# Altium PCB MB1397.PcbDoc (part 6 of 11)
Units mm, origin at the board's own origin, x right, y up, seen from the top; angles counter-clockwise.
Board outline 118.24 x 172.86 mm, 6 copper layers (Top Layer, L2_GND, L3_VCC, L4_SIG, L5_GND, Bottom Layer), stack 1.631 mm thick; 819 components, 632 nets, 2875 pads, 1523 vias.
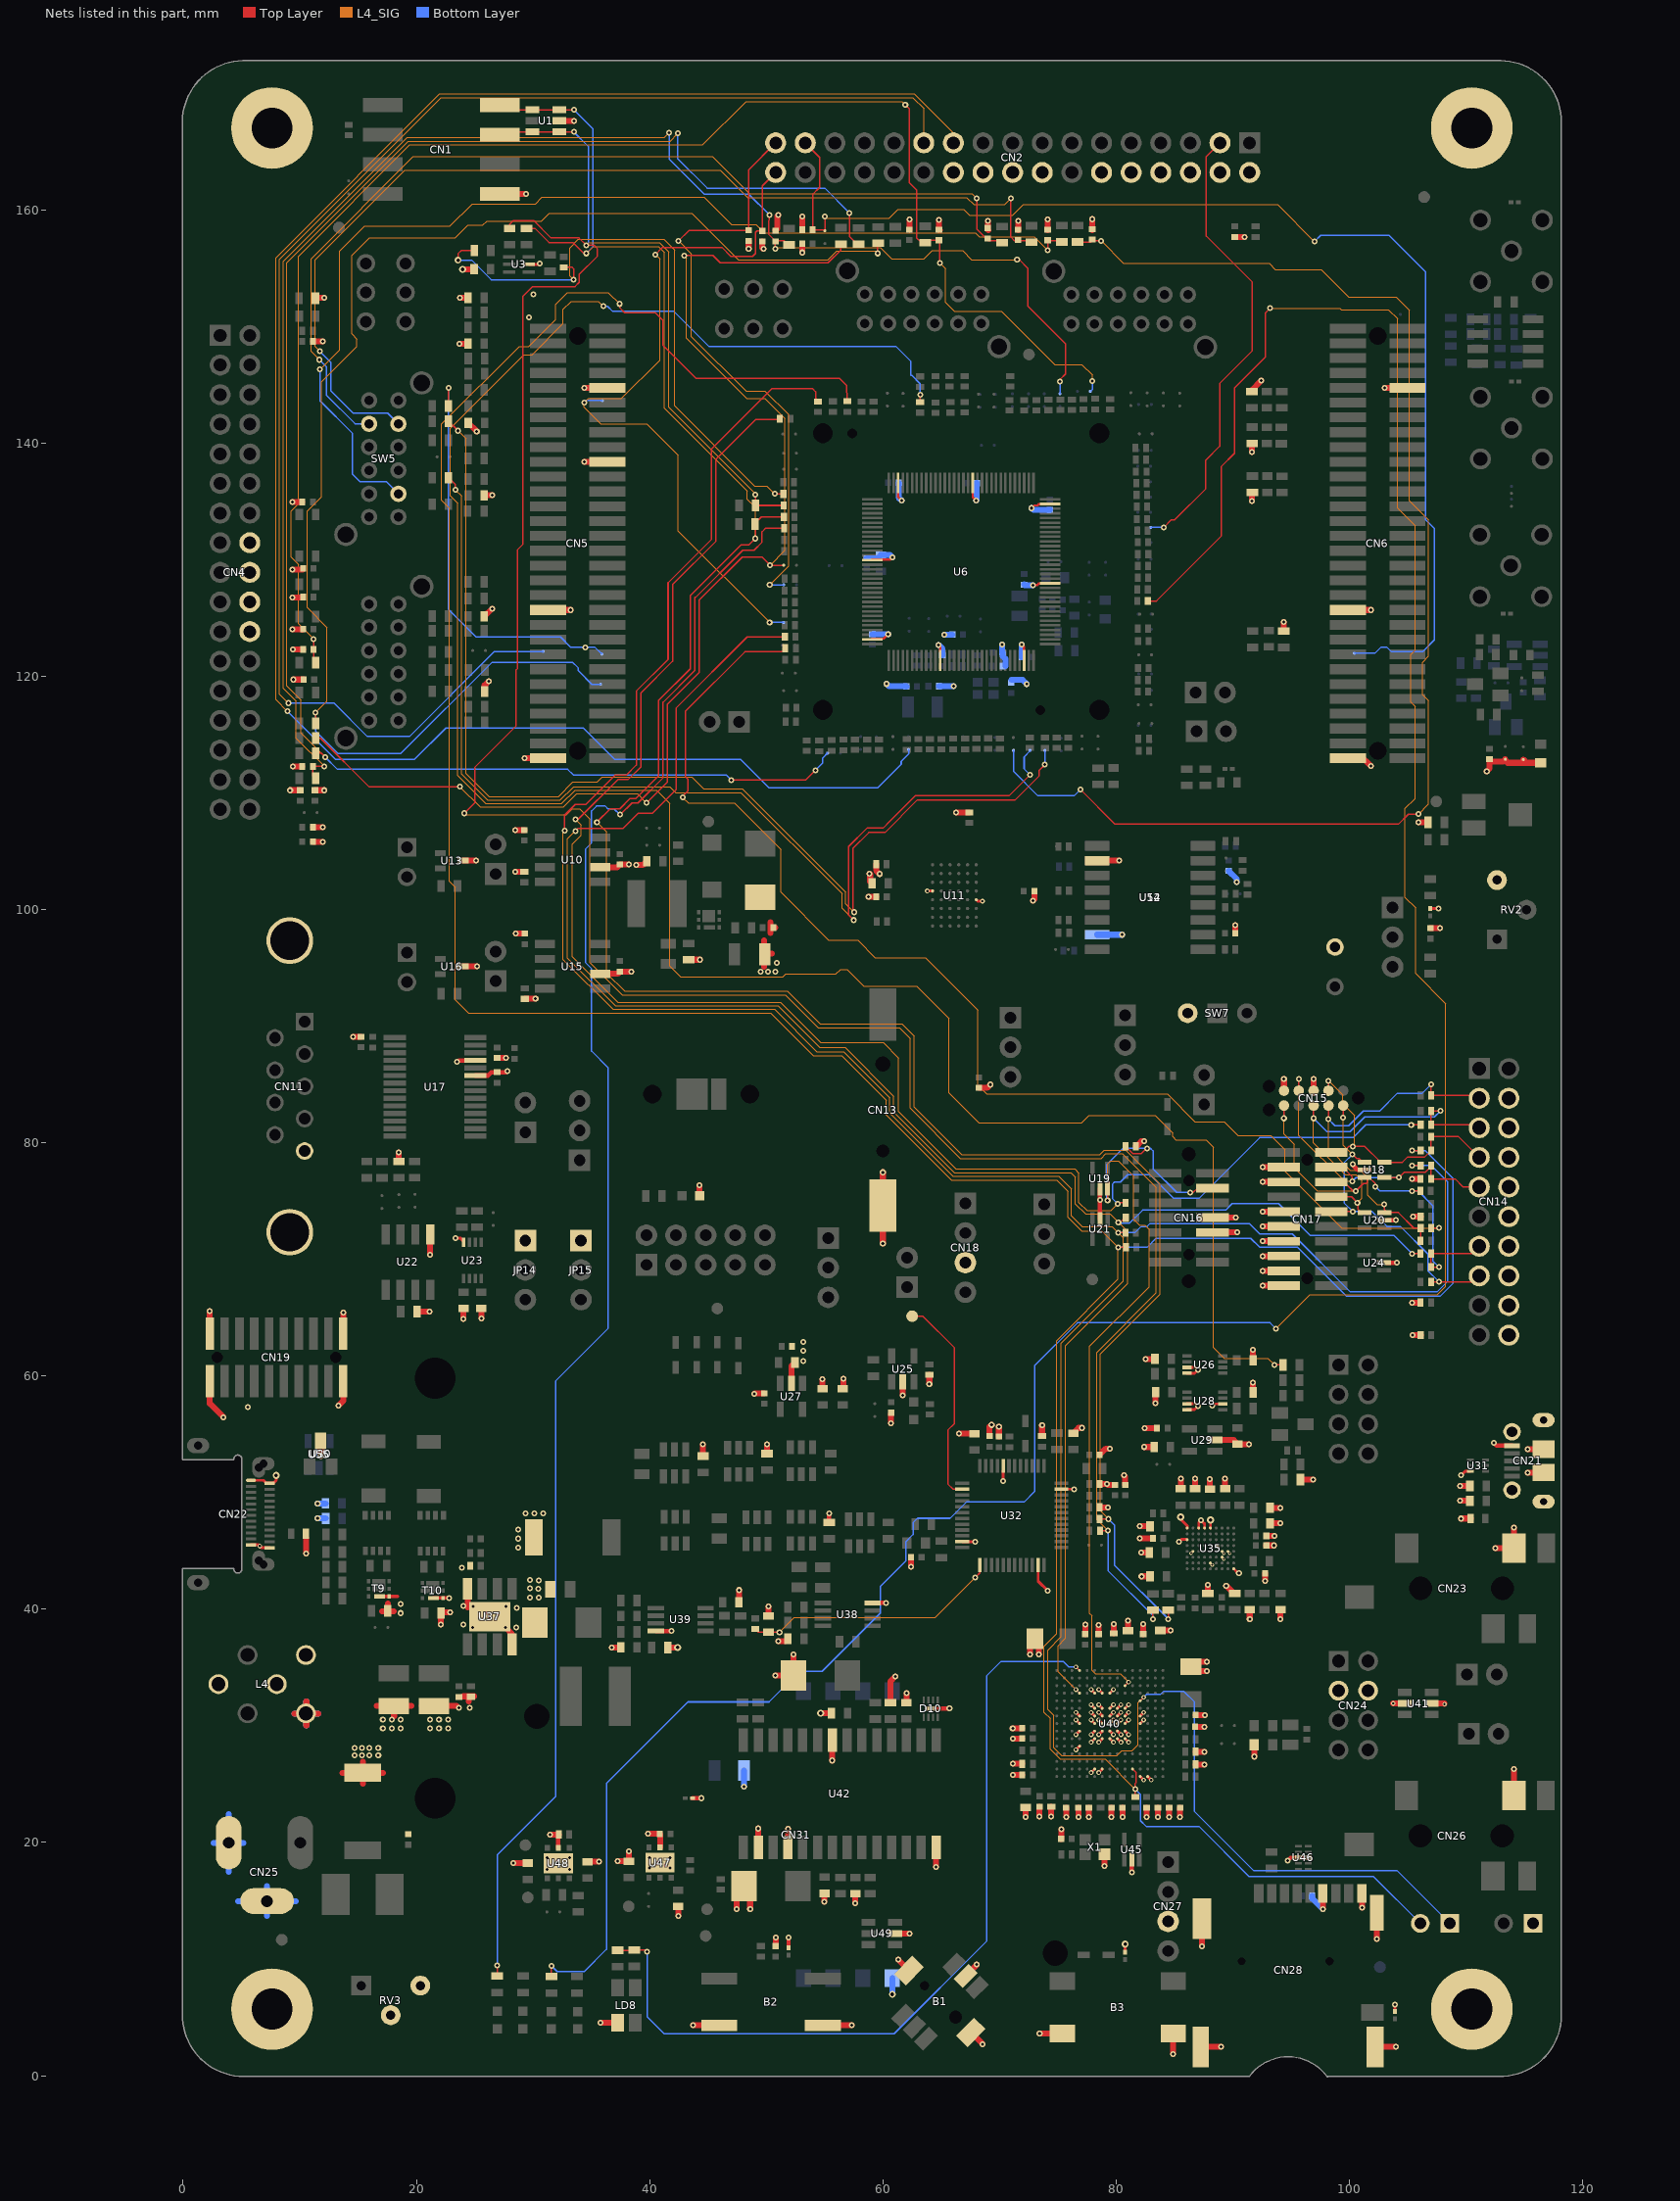
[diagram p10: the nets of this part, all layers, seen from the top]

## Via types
v1: diameter 0.508, hole 0.254, Top Layer to Bottom Layer, tented both sides, 1330 vias
v2: diameter 0.406, hole 0.203, Top Layer to Bottom Layer, tented both sides, 115 vias
v3: diameter 0.508, hole 0.254, Top Layer to Bottom Layer, 33 vias
v4: diameter 0.305, hole 0.152, Top Layer to Bottom Layer, tented both sides, 26 vias
v5: diameter 0.61, hole 0.305, Top Layer to Bottom Layer, tented both sides, 14 vias
v6: diameter 0.61, hole 0.33, Top Layer to Bottom Layer, tented both sides, 2 vias
v7: diameter 0.381, hole 0.203, Top Layer to Bottom Layer, tented both sides, 2 vias
v8: diameter 0.508, hole 0.203, Top Layer to Bottom Layer, tented both sides, 1 vias

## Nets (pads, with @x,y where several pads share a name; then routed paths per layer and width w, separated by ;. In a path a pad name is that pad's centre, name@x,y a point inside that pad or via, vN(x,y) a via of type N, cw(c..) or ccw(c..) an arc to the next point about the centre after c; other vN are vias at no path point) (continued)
GND: B1.5 B1.7 B1.8 B2.3 B2.4 B3.1 B3.2 C1.1 C2.1 C3.1 C4.2 C5.1 C6.1 C7.1 C8.1 C9.1 C10.1 C11.1 C12.1 C13.2 C14.2 C15.2 C16.1 C18.2 C21.2 C22.2 C23.1 C24.1 C25.2 C26.1 C29.1 C31.1 C32.2 C33.2 C34.1 C37.1 C38.1 C39.1 C40.2 C41.2 C42.1 C44.2 C45.1 C46.1 C47.2 C48.2 C49.1 C50.2 C51.1 C52.2 C53.2 C54.1 C56.1 C58.2 C59.1 C61.2 C62.1 C63.1 C64.2 C65.1 C66.2 C67.1 C68.1 C69.2 C70.1 C71.1 C72.1 C73.1 C74.1 C75.1 C76.1 C77.1 C78.1 C79.1 C80.1 C81.2 C82.2 C83.1 C84.1 C85.2 C86.1 C88.1 C89.1 C90.1 C91.1 C92.1 C93.2 C94.2 C96.2 C97.1 C98.1 C100.2 C101.1 C102.1 C104.1 C105.1 C108.1 C109.2 C112.1 C113.1 C114.1 C115.1 C116.1 C117.1 C118.1 C119.1 C120.1 C121.2 C122.1 C123.1 C124.1 C125.1 C126.2 C127.1 C128.1 C130.1 C131.1 C133.1 C134.1 C135.1 C136.1 C137.1 C138.1 C139.1 C140.1 C141.1 C142.1 C143.1 C144.1 C145.1 C146.2 C148.1 C149.1 C150.2 C151.1 C152.2 C153.1 C155.2 C156.1 C157.1 C160.1 C161.1 C162.1 C163.2 C164.1 C165.1 C172.2 C173.1 C174.1 C175.1 C176.1 C177.1 C178.1 C182.1 C183.1 C184.1 C185.1 C186.2 CN1.7 CN2.2 CN2.4 CN2.6 CN2.8 CN2.10 CN2.12 CN2.16 CN2.18 CN2.20 CN2.22 CN4.16 CN4.18 CN4.20 CN4.22 CN5.10 CN5.20 CN5.39 CN5.59 CN6.10 CN6.39 CN6.59 CN11.5 CN11.MT1 CN11.MT2 CN13.2 CN14.4 CN14.6 CN14.8 CN14.10 CN14.12 CN14.14 CN14.16 CN14.18 CN14.20 CN15.3 CN15.5 CN16.5 CN16.7 CN17.3 CN17.5 CN17.9 CN17.11 CN17.13 CN17.15 CN17.17 CN17.19 CN18.3 CN19.1 CN19.2 CN19.19 CN19.20 CN21.5 CN21.6 CN21.7 CN21.8 CN21.9 CN21.10 CN21.11 CN22.A1 CN22.A12 CN22.B1 CN22.B12 CN23.3 CN24.3 CN24.4 CN26.3 CN27.3 CN28.6 CN28.9 CN28.11 CN28.12 CN28.13 CN28.14 CN30.1 CN31.C5 CN31.S1 D10.9 H1.1 H2.1 H5.1 H6.1 JP14.1 JP15.1 L1.1 L4.4 L4.5 L4.6 L7.1 LD6.2 LD8.1 R18.2 R32.1 R56.1 R65.1 R106.1 R156.1 R157.2 R162.1 R163.2 R174.2 R176.1 R177.1 R180.2 R187.1 R190.2 R195.1 R203.1 R212.1 R213.1 R214.1 R217.1 R224.1 R229.1 R230.1 R233.2 R234.2 R236.2 R242.1 R251.1 R255.1 R256.1 R263.1 R264.1 R269.1 R271.1 R272.1 R276.1 R279.1 R280.1 R281.2 R283.1 R286.2 R323.1 RV2.3 RV3.2 RV3.3 SB30.1 SB31.1 SW7.3 T9.4 T9.7 T10.4 T10.7 U1.2 U3.5 U6.12 U6.30 U6.46 U6.63 U6.78 U6.94 U6.110 U6.127 U10.2 U11.D1 U11.E6 U12.10 U13.3 U14.2 U15.2 U16.3 U17.23 U17.25 U18.2 U19.2 U20.2 U21.2 U22.5 U23.4 U24.2 U25.2 U26.3 U26.4 U27.2 U28.3 U28.4 U28.6 U29.2 U30.3 U31.3 U32.8 U32.23 U32.35 U32.47 U33.2 U34.2 U35.A1 U35.A3 U35.A4 U35.A5 U35.C1 U35.D6 U35.E2 U35.E7 U35.E8 U35.F7 U35.G5 U35.H9 U36.2 U37.4 U37.8 U37.9 U38.4 U39.4 U40.D5 U40.D7 U40.D8 U40.D9 U40.F2 U40.F6 U40.F7 U40.F8 U40.F9 U40.F10 U40.F12 U40.G2 U40.G6 U40.G7 U40.G8 U40.G9 U40.G10 U40.G12 U40.H6 U40.H7 U40.H8 U40.H9 U40.H10 U40.H12 U40.J6 U40.J7 U40.J8 U40.J9 U40.J10 U40.K6 U40.K7 U40.K8 U40.K9 U40.K10 U40.M1 U40.M8 U40.M9 U40.N1 U41.2 U41.5 U42.2 U42.4 U42.14 U42.22 U44.2 U45.2 U46.3 U46.8 U47.2 U47.EP U48.2 U48.EP U49.2 U50.2 U51.2 U52.2 U54.10 U55.2 X1.2 | length 399.3
  Top Layer w0.127: v4(86.416,44.806) U35.E2@86.577,44.966 ; U35.G5@88.077,43.966 v4(88.237,43.805) ; U35.D6@88.577,45.466 88.577,45.463 v4(88.735,45.306) ; U35.F7@89.077,44.466 v4(89.235,44.305) ; U35.E7@89.077,44.966 v4(89.235,44.806) ; U35.E8@89.577,44.966 v4(89.736,44.806)
  Top Layer w0.203: U6.127@59.083,123.22 60.058,123.22 v1(60.452,123.614) ; U6.110@59.083,130.021 60.628,130.021 v1(60.808,130.2) ; U6.94@61.303,136.586 61.303,135.367 v1@61.595,135.075 ; v1(64.77,122.682) 64.902,122.547 U6.12@64.902,122.098 ; U6.78@67.701,135.992 67.701,135.367 v1(67.993,135.075) ; v1(71.89,122.735) 72.074,122.551 U6.30@72.074,121.916 ; v1(72.743,134.414) 72.974,134.645 73.257,134.645 73.377,134.765 U6.63@73.66,134.765 ; v1(72.87,127.81) 73.217,127.81 73.348,127.941 U6.46@73.515,127.941 ; U6.63@74.322,134.765 U6.63@74.323,134.766
  Top Layer w0.229: CN22.B12@5.816,51.054 6.878,51.054 CN22.A1@7.13,50.803 ; U32.23@66.807,45.792 v1(67.917,45.791) ; 73.307,42.41 U32.35@73.307,43.79 ; U32.47@75.307,50.292 v1(76.378,50.292) ; v1(85.392,45.794) 85.595,45.997 86.042,45.997 U35.C1@86.077,45.966 U35.C1@86.078,45.964 ; U35.A3@87.077,46.966 87.076,47.427 v1(87.272,47.622) 87.526,47.366 87.577,47.366 U35.A4@87.577,46.966 ; U35.A5@88.077,46.966 v5(88.077,47.648) ; v1(88.237,57.452) 88.4,57.615 U28.6@89.152,57.616 ; U35.H9@90.077,43.466 90.439,43.101 v1(90.523,43.101)
  Top Layer w0.254: CN22.B12@5.814,51.054 CN22.B12@5.816,51.054 ; CN22.B1@5.816,45.514 5.817,45.514 6.474,45.514 v2(6.576,45.413) 6.726,45.263 CN22.A12@7.414,45.263 ; CN22.A1@7.13,50.803 7.719,50.803 7.973,51.057 v5(7.973,51.483) ; v1(23.34,71.803) 23.797,71.803 24.051,71.549 U23.4@24.051,71.472 ; U3.5@29.632,155.321 30.505,155.321 v1(30.582,155.397) ; v2(63.802,101.585) U11.E6@64.249,101.585 ; U11.D1@67.999,100.835 68.12,100.711 v2(68.529,100.711) ; v1(70.307,50.998) U32.8@70.307,51.859 ; 73.307,42.41 v1(74.14,41.577) ; v2(76.551,29.249) U40.D7@76.853,29.551 ; v2(76.551,30.505) U40.D8@76.853,30.203 ; v2(76.551,31.155) U40.D9@76.853,30.853 ; v2(76.552,27.949) U40.D5@76.855,28.251 ; v2(77.851,30.505) U40.F8@78.155,30.203 ; v2(77.851,31.155) U40.F9@78.155,30.853 ; v2(77.851,31.805) U40.F10@78.155,31.503 ; v2(77.851,33.105) U40.F12@78.155,32.803 ; v2(77.852,26) U40.F2@78.155,26.303 ; v2(77.852,28.599) U40.F6@78.155,28.901 ; v2(77.852,29.249) U40.F7@78.155,29.553 ; v2(78.501,30.505) U40.G8@78.805,30.203 ; v2(78.501,31.155) U40.G9@78.805,30.853 ; v2(78.501,31.805) U40.G10@78.805,31.503 ; v2(78.501,33.105) U40.G12@78.805,32.803 ; v2(78.502,26) U40.G2@78.805,26.303 ; v2(78.502,28.599) U40.G6@78.805,28.901 ; v2(78.502,29.249) U40.G7@78.805,29.553 ; U40.H8@79.455,30.203 v2(79.757,30.505) ; U40.H9@79.455,30.853 v2(79.757,31.155) ; U40.H10@79.455,31.503 v2(79.757,31.805) ; U40.H12@79.455,32.803 v2(79.757,33.106) ; U40.H6@79.456,28.903 v2(79.758,28.6) ; U40.H7@79.456,29.553 v2(79.758,29.25) ; U40.J8@80.105,30.203 v2(80.407,30.505) ; U40.J9@80.105,30.853 v2(80.407,31.155) ; U40.J10@80.105,31.503 v2(80.407,31.805) ; U40.J6@80.106,28.903 v2(80.408,28.6) ; U40.J7@80.106,29.553 v2(80.408,29.25) ; U40.K8@80.755,30.203 v2(81.057,30.505) ; U40.K9@80.755,30.853 v2(81.057,31.155) ; U40.K10@80.755,31.503 v2(81.057,31.805) ; U40.K6@80.755,28.903 v2(81.058,28.6) ; U40.K7@80.755,29.553 v2(81.058,29.25) ; U51.2@80.767,10.582 v5(80.767,11.286) ; U40.M1@82.055,25.653 v2(82.357,25.35) ; U40.M8@82.055,30.203 v2(82.357,30.505) ; U40.M9@82.055,30.853 v2(82.357,31.155) ; U40.N1@82.705,25.653 v2(83.007,25.35) ; v5(85.519,47.902) 85.519,47.724 86.076,47.168 U35.A1@86.077,46.966 ; U28.4@86.052,57.116 86.726,57.114 v1(87.018,57.407) 86.81,57.615 U28.3@86.052,57.616 ; U26.4@86.051,60.235 86.726,60.234 v1(87.018,60.526) 86.81,60.734 U26.3@86.051,60.735 ; U52.2@103.886,5.519 v1(103.886,6.116) ; U14.2@106.934,100.085 v1(107.627,100.084) ; v1(109.573,51.483) 109.906,51.816 U31.3@110.354,51.816
  Top Layer w0.305: T9.7@16.843,41.09 18.367,41.09 ; T10.7@21.458,40.963 T10.4@22.283,40.963 v1(22.812,40.963) ; U50.2@51.914,10.98 v1(51.913,11.857) ; v1(94.714,18.463) 94.948,18.697 U46.3@96.452,18.699
  Top Layer w0.381: v1(23.492,86.942) 23.612,87.061 U17.25@25.04,87.063 ; U17.23@25.04,85.763 26.134,85.763 26.419,86.048 27.678,86.048 v1(27.785,86.154) ; U48.2@32.166,19.524 32.167,20.648 R286.2@32.205,20.688 ; U39.4@40.531,38.138 v1(41.882,38.138) ; U44.2@43.668,23.8 v1(44.425,23.8) ; R242.1@55.39,47.436 v1(55.39,48.227) ; U38.4@59.098,40.541 v1(60.274,40.538) ; D10.9@64.094,31.483 64.107,31.496 v1(65.703,31.496) ; U19.2@78.606,76.077 v1(78.605,75.095) 78.613,75.087 U21.2@78.613,73.446 U21.2@78.613,73.446 ; v1(81.336,17.447) U45.2@81.336,18.536 ; v1(100.302,78.153) 100.302,78.057 100.683,77.676 U18.2@101.542,77.676 ; U24.2@103.21,69.718 v1(104.059,69.718) ; U20.2@103.243,73.358 v1(103.985,73.358) ; v1(112.367,54.277) 112.624,54.021 CN21.5@113.938,54.021
  Top Layer w0.508: CN19.1@2.286,59.56 2.286,57.63 3.452,56.464 v1(3.454,56.464) ; CN19.2@2.286,63.63 v1(2.286,65.552) ; v1(9.177,110.223) C37.1@10.044,110.223 ; v1(9.37,124.003) 10.19,124.003 C26.1@10.19,124 ; v1(9.37,126.746) C24.1@10.234,126.746 ; v1(9.37,129.159) C23.1@10.234,129.159 ; v1(9.37,134.94) C22.2@10.218,134.941 ; v1(9.418,112.268) C34.1@10.218,112.268 ; v1(9.418,122.301) C29.1@10.285,122.301 ; v1(9.464,119.715) C31.1@10.335,119.717 ; v1(10.526,44.764) U36.2@10.526,46.129 ; C42.1@11.118,105.791 v1(11.958,105.791) ; C39.1@11.118,107.06 v1(11.961,107.058) ; C16.1@11.118,148.709 v1(11.979,148.707) ; C38.1@11.294,110.223 v1(12.098,110.223) ; R18.2@11.339,152.448 v1(12.113,152.448) ; v1(11.783,53.134) U30.3@11.783,54.234 ; v1(13.307,57.452) 13.716,57.861 CN19.19@13.716,59.56 ; CN19.20@13.716,63.63 v1(13.716,65.453) ; v1(14.577,89.096) C54.1@15.24,89.096 ; 16.604,31.702 C124.1@18.082,31.702 ; 17.046,39.825 R263.1@17.544,39.825 ; 17.544,40.503 R263.1@17.544,39.825 ; 18.042,39.825 R263.1@17.544,39.825 ; 18.082,30.823 C124.1@18.082,31.702 ; R190.2@18.501,78.409 v1(18.499,79.169) ; 19.561,31.702 C124.1@18.082,31.702 ; R213.1@20.047,65.532 R213.1@20.047,65.532 v1(21.133,65.532) ; C123.1@20.46,31.702 23.416,31.702 ; v1(21.176,70.411) U22.5@21.177,72.141 ; v1(22.108,38.694) 22.108,39.731 v1(22.901,39.731) ; v1(23.67,148.511) C15.2@24.417,148.511 ; v1(23.721,152.448) C14.2@24.413,152.448 C14.2@24.417,152.448 ; v5(23.952,154.889) 23.96,154.897 C13.2@24.951,154.897 ; U16.3@23.998,95.124 v1(25.197,95.123) ; U13.3@23.999,104.185 v1(25.113,104.183) ; 24.026,32.535 R272.1@24.486,32.535 ; v1(24.039,64.882) C61.2@24.039,65.787 ; 24.384,40.144 U37.4@24.384,41.736 ; C18.2@24.446,141.732 v1(25.176,141) ; 24.486,32.103 R272.1@24.486,32.535 ; R272.1@24.943,32.535 R272.1@24.486,32.535 ; v1(25.563,64.945) C62.1@25.563,65.782 ; C21.2@25.813,135.509 v1(26.515,135.509) ; C25.2@25.821,125.12 v1(26.485,125.783) ; C32.2@25.847,118.684 25.847,119.217 v1(26.21,119.581) ; C56.1@26.924,87.263 v1(27.658,87.262) ; CN1.7@27.135,161.349 v1(29.411,161.348) ; v1(27.632,38.439) 28.194,37.877 U37.8@28.194,36.986 ; v1(28.324,18.24) C151.1@29.55,18.24 ; v1(28.463,106.812) C40.2@29.25,106.814 ; v1(28.489,103.231) R163.2@29.25,103.232 ; v1(28.505,97.93) C52.2@29.303,97.93 ; v1(29.284,112.979) CN5.59@31.285,112.981 ; R180.2@29.303,92.338 v1(30.216,92.338) ; CN5.39@31.285,125.681 v1(33.216,125.679) ; v1(31.468,20.688) R286.2@32.205,20.688 ; U1.2@32.247,167.627 v1(33.5,167.625) ; v1(34.389,138.382) 36.386,138.382 CN5.20@36.385,138.381 ; v1(34.389,144.732) 36.386,144.732 CN5.10@36.385,144.731 ; C150.2@34.663,18.356 v1(35.672,18.354) ; U15.2@35.761,94.489 37.264,94.488 C53.2@37.45,94.674 v1(38.443,94.673) ; U10.2@35.761,103.631 37.224,103.629 C44.2@37.45,103.856 v1(38.199,103.856) ; v1(35.786,4.549) LD8.1@37.256,4.55 ; v1(36.733,36.722) C120.1@37.519,36.723 ; v1(37.254,18.392) C149.1@38.215,18.394 v1(38.214,19.241) ; v1(38.834,103.807) 39.398,103.807 C45.1@39.742,104.151 ; v1(39.858,20.742) C146.2@40.873,20.742 40.891,20.721 U47.2@40.892,19.577 ; R271.1@41.569,36.722 v5(42.39,36.722) ; v1(42.456,13.698) C156.1@42.456,14.453 ; R176.1@43.325,95.692 R176.1@43.325,95.694 v1(44.295,95.695) ; v1(43.708,4.318) B2.3@45.964,4.318 ; LD6.2@44.284,75.442 v1(44.282,76.375) ; R230.1@44.549,53.198 v1(44.549,54.15) ; v1(47.47,14.272) 47.47,15.624 C152.2@48.095,16.25 48.613,15.73 v1(48.613,14.272) ; C108.1@47.655,40.607 v1(47.655,41.646) ; v1(48.486,156.639) C9.1@48.486,157.335 ; v1(48.977,58.468) 49.025,58.516 C71.1@49.817,58.516 ; U42.2@49.313,19.585 49.314,19.583 v1(49.314,21.196) ; C11.1@49.654,157.281 49.654,156.741 v1(49.756,156.639) ; 49.804,95.105 R177.1@49.804,96.233 ; 49.804,97.361 R177.1@49.804,96.233 ; R229.1@50.069,53.34 v1(50.068,54.15) ; C112.1@50.189,39.435 v1(50.188,40.231) ; 50.35,97.986 C49.1@50.35,98.445 ; 50.35,98.903 C49.1@50.35,98.445 ; 50.482,96.233 R177.1@49.804,96.233 ; v1(50.772,34.313) C121.2@52.336,34.313 v1(52.337,36.116) ; C10.1@50.772,158.232 50.924,158.384 50.924,159.459 v1(51.026,159.56) ; C49.1@50.782,98.445 C49.1@50.35,98.445 ; C157.1@50.8,11.118 v1(50.8,11.859) ; v1(51.026,37.259) 51.628,37.259 C119.1@51.839,37.472 ; U42.4@51.853,19.585 51.854,19.583 v1(51.854,21.191) ; U27.2@52.154,59.352 52.154,60.859 C66.2@52.451,61.156 ; v1(53.076,156.334) C12.1@53.077,157.087 ; C3.1@53.077,158.287 v1(53.076,159.433) ; v5(54.662,31.088) C127.1@55.577,31.088 ; C67.1@54.821,58.931 v1(54.821,59.738) ; B2.4@54.864,4.318 v1(57.328,4.318) ; v1(54.963,14.907) C153.1@54.963,15.603 ; U42.22@55.663,28.765 55.664,28.763 v1(55.664,27.033) ; C68.1@56.596,58.989 v1(56.596,59.756) ; v1(57.63,14.78) C155.2@57.63,15.604 ; v1(58.773,101.089) 59.426,101.089 C48.2@59.426,101.088 ; v1(58.849,103.081) 58.9,103.03 58.9,102.41 C46.1@59.057,102.256 ; R162.1@59.416,103.885 59.416,103.342 v1(59.713,103.045) ; v1(59.992,71.371) CN13.2@59.992,74.604 v1(59.992,77.467) ; R276.1@60.657,31.987 60.657,33.834 v1(61.062,34.239) ; v1(60.681,55.928) C72.1@60.681,56.759 ; U49.2@61.049,12.192 v1(62.281,12.192) ; v1(61.313,9.944) B1.7@62.237,9.021 ; v1(61.699,58.341) U25.2@61.699,59.484 ; C126.2@62.013,31.988 62.014,31.986 v1(62.014,32.814) ; C5.1@62.271,158.295 v1(62.271,159.154) ; v1(62.408,43.658) C98.1@62.408,44.455 ; v1(63.98,59.294) R217.1@63.98,60.093 ; U42.14@64.553,19.585 64.554,19.583 v1(64.554,17.894) ; v1(64.8,159.121) 64.8,158.3 C7.1@64.869,158.232 ; v1(66.269,108.321) R156.1@67.41,108.322 ; v1(66.52,55.052) C76.1@67.861,55.053 ; B1.8@67.541,3.718 67.541,3.719 v1(68.542,2.715) ; v1(68.044,9.525) B1.5@67.081,8.562 ; C59.1@68.227,84.698 68.923,84.696 v1(69.212,84.986) ; v1(68.981,159.052) 68.981,158.311 C2.1@69.06,158.232 ; C77.1@69.145,54.845 69.144,55.631 v1(69.314,55.801) ; C78.1@69.945,54.803 v1(69.944,55.669) ; v1(71.123,29.797) C131.1@71.951,29.799 ; v1(71.125,28.91) C133.1@71.943,28.912 ; v1(71.133,25.796) C134.1@71.951,25.798 ; v1(71.133,26.749) R280.1@71.951,26.751 ; v1(71.587,159.04) 71.587,158.245 C6.1@71.6,158.234 ; v1(72.233,22.177) C135.1@72.233,23.003 ; v1(72.616,36.116) 72.616,37.056 C115.1@73.033,37.472 73.378,37.125 v1(73.378,36.116) ; v1(72.87,100.759) 72.984,100.874 72.984,101.572 C47.2@72.983,101.573 ; v1(73.416,22.243) C136.1@73.417,23.068 ; v1(73.431,3.632) 75.382,3.632 B3.2@75.39,3.625 ; R224.1@73.644,54.844 v1(73.642,55.791) ; v1(74.127,159.167) 74.127,158.372 74.14,158.359 C8.1@74.14,158.232 ; v1(74.432,22.243) R283.1@74.433,23.068 ; C148.1@75.28,20.31 75.281,20.31 v1(75.281,21.125) ; v1(75.702,22.174) C138.1@75.703,22.999 ; C75.1@76.313,55.095 76.766,55.547 v1(77.061,55.547) ; v1(76.756,22.174) C139.1@76.758,22.999 ; C116.1@77.346,37.869 v1(77.346,38.687) ; v1(77.645,22.174) C140.1@77.647,22.999 ; v1(77.937,159.192) 77.937,158.245 C4.2@77.95,158.232 ; U12.10@78.351,104.188 v1(80.236,104.188) ; C117.1@78.496,37.869 v1(78.496,38.656) ; R236.2@78.579,48.738 v1(79.296,48.738) ; R234.2@78.579,50.741 78.577,50.742 v1(79.2,50.742) 79.276,50.665 C82.2@79.855,50.665 ; C80.1@78.579,53.238 79.111,53.769 v1(79.474,53.769) ; v1(78.989,17.978) X1.2@78.988,18.981 ; v1(79.591,22.174) C141.1@79.59,22.999 ; R269.1@79.797,37.922 v1(79.797,38.725) ; v1(80.538,22.174) C137.1@80.54,22.999 ; v1(80.668,51.483) 80.668,51.432 80.744,51.356 C83.1@80.744,50.665 ; C114.1@81.011,38.172 v1(81.011,39.025) ; R187.1@81.697,79.708 81.74,79.708 82.166,80.134 v1(82.395,80.134) ; v1(82.014,46.076) C94.2@83.147,46.077 ; v1(82.014,47.117) C92.1@82.897,47.119 ; v1(82.136,44.879) C97.1@82.837,44.879 ; v1(82.166,42.822) C101.1@82.897,42.822 ; C118.1@82.306,37.869 v1(82.306,38.745) ; v1(82.385,53.912) 83.254,53.912 C79.1@83.254,53.911 ; v1(82.441,55.527) C74.1@83.504,55.527 ; v1(82.522,61.463) C64.2@83.321,61.464 ; v1(82.606,22.174) C145.1@82.607,22.999 ; v1(83.37,57.671) C69.2@83.371,58.619 ; v1(83.576,22.174) C142.1@83.577,22.999 ; C113.1@83.782,38.186 C113.1@83.782,38.186 v1(84.681,38.184) ; v1(84.539,22.174) 84.539,22.997 C143.1@84.541,22.999 ; v1(84.89,1.875) B3.1@84.89,3.625 ; v1(85.471,22.174) C144.1@85.471,22.999 ; C84.1@85.529,50.326 85.529,50.325 v1(85.529,51.189) ; C122.1@86.402,35.075 86.782,34.694 v1(87.754,34.694) ; C122.1@86.402,35.075 86.81,35.481 v1(87.78,35.481) ; C85.2@86.763,50.326 v1(86.761,51.189) ; C130.1@86.782,29.918 v1(87.579,29.916) ; R281.2@86.821,26.69 v1(87.572,26.688) ; R279.1@86.821,27.778 v1(87.559,27.777) ; C128.1@86.821,30.926 v1(87.587,30.925) ; CN28.12@87.248,2.475 v1(88.999,2.474) ; v1(87.348,11.097) CN28.13@87.348,13.475 ; R256.1@87.84,41.356 v1(87.838,42.085) ; C88.1@88.04,50.301 v1(88.039,51.163) ; CN16.5@88.258,72.307 v1(90.391,72.306) ; CN16.7@88.258,73.577 v1(90.264,73.576) ; U29.2@88.464,54.509 90.061,54.508 C73.1@90.412,54.157 ; C86.1@89.339,50.326 89.339,50.325 v1(89.339,51.189) ; v1(89.431,42.009) 90.086,41.354 R255.1@90.152,41.356 ; C1.1@90.17,157.665 v1(91.023,157.663) ; C51.1@90.212,97.966 v1(90.211,98.651) ; C73.1@90.412,54.157 v1(91.387,54.155) ; v1(91.448,39.164) C105.1@91.448,39.956 ; v1(91.641,139.205) R56.1@91.641,139.906 ; v1(91.646,135.029) R65.1@91.646,135.824 ; R32.1@91.646,144.424 91.646,144.554 v1(92.428,145.336) ; C70.1@91.731,58.594 v1(91.73,59.446) ; C65.1@91.731,61.337 v1(91.73,62.24) ; v1(91.834,27.368) L7.1@91.834,28.385 ; v1(92.555,67.742) CN17.19@94.358,67.743 ; v1(92.555,69.012) CN17.17@94.358,69.013 ; v1(92.555,70.282) CN17.15@94.358,70.283 ; v1(92.555,71.552) CN17.13@94.358,71.553 ; v1(92.555,72.822) CN17.11@94.358,72.823 ; v1(92.555,74.092) CN17.9@94.358,74.093 ; v1(92.555,76.632) CN17.5@94.358,76.633 ; v1(92.555,77.902) CN17.3@94.358,77.903 ; v1(92.751,42.408) C100.2@92.751,43.101 ; C96.2@92.85,45.469 v1(93.525,45.469) ; C93.2@92.878,46.276 v1(93.571,46.276) ; C91.1@93.187,47.373 v1(94.079,47.371) ; C90.1@93.187,48.701 v1(94.069,48.699) ; v1(94.079,39.164) C104.1@94.079,39.954 ; R106.1@94.349,123.867 v1(94.348,124.661) ; CN15.5@94.384,84.463 v1(94.384,85.468) ; R233.2@95.798,51.13 R233.2@95.798,51.13 v1(96.871,51.13) ; CN15.3@96.924,84.463 v1(96.924,85.468) ; v1(97.721,14.272) CN28.6@97.723,15.625 ; CN6.59@99.865,112.981 101.163,112.979 101.57,112.57 101.572,112.57 v1(101.826,112.316) ; CN6.39@99.865,125.681 v1(101.826,125.679) ; v1(101.072,14.399) CN28.9@101.073,15.625 ; CN28.11@102.198,2.475 v1(103.972,2.474) ; v1(102.347,11.72) CN28.14@102.347,13.973 ; v1(103.033,144.729) CN6.10@104.965,144.731 ; v7(103.736,31.925) U41.2@104.74,31.925 ; v1(105.382,66.294) R212.1@106.091,66.294 ; v1(105.382,76.896) R195.1@106.091,76.898 ; v1(105.395,63.5) R214.1@106.103,63.5 ; v1(105.461,73.66) R203.1@106.103,73.66 ; v1(105.903,107.478) R157.2@106.742,107.479 ; C50.2@106.934,98.398 v1(107.744,98.397) ; U41.5@107.04,31.925 108.142,31.925 v7(108.142,31.877) ; v1(109.469,49.301) C89.1@110.327,49.302 ; v1(109.469,50.571) C81.2@110.327,50.572 ; v1(109.55,47.777) U34.2@110.402,47.778 ; v1(111.773,111.847) 112.003,112.078 C33.2@112.003,112.665 ; C33.2@112.033,112.885 C33.2@112.033,112.854 ; v1(112.494,45.232) CN23.3@114.11,45.233 v1(114.109,46.998) ; CN26.3@114.091,24.024 v1(114.089,26.292) ; SB31.1@114.907,112.86 115.188,112.579 ; v1(115.28,51.719) CN21.10@116.638,51.721 ; v1(115.291,53.721) CN21.11@116.638,53.721 ; L1.1@116.383,112.579 115.188,112.579 ; B1.5@67.081,8.562 B1.5@67.081,8.562 B1.5@67.081,8.562 ; C33.2@112.003,112.665 112.033,112.696 C33.2@112.033,112.854 ; C33.2@112.003,112.665 C33.2@112.003,112.885 C33.2@112.033,112.854 ; C33.2@112.033,112.854 112.192,112.696 113.182,112.696 SB30.1@113.365,112.879 113.365,112.782 113.569,112.579 115.188,112.579
  Bottom Layer w0.127: 71.971,119.692 71.971,119.698 ; v8@72.329,119.278 v8(72.329,119.334)
  Bottom Layer w0.508: v1(11.529,47.8) R323.1@12.225,47.8 ; v1(11.529,49.07) C185.1@12.225,49.07 ; U55.2@11.656,54.158 11.656,53.261 v1(11.783,53.134) ; v1(48.101,24.785) CN31.S1@48.101,26.165 ; C164.1@58.603,130.116 59.538,130.114 C163.2@59.817,130.392 60.617,130.391 v1(60.808,130.2) ; C173.1@59.083,123.616 v1(60.452,123.614) ; v1(60.322,119.339) 60.509,119.153 61.982,119.153 C183.1@62.009,119.126 ; v5(60.801,6.985) CN31.C5@60.801,8.365 ; C160.1@61.353,136.586 61.351,135.313 v1(61.592,135.075) ; v1(64.77,122.682) 65.1,122.352 C175.1@65.1,121.786 ; C182.1@64.798,119.151 v1(66.063,119.151) ; v1(65.278,123.571) C172.2@65.953,123.571 ; v1(67.993,135.075) 68.052,135.136 C161.1@68.053,136.566 ; v1(70.234,122.715) 70.234,122.062 C174.1@70.275,122.022 70.274,121.722 70.503,121.493 C177.1@70.503,120.866 ; C178.1@71.003,119.698 71.971,119.698 ; C176.1@71.889,121.638 v1(71.89,122.735) ; 71.971,119.692 v8(72.329,119.334) ; C165.1@72.108,127.869 72.166,127.81 v1(72.87,127.81) ; v1(72.743,134.414) 72.893,134.264 C162.1@74.323,134.266 ; U54.10@78.351,97.838 v1(80.49,97.838) ; C184.1@89.644,103.312 C184.1@89.645,103.31 90.335,102.619 v1(90.335,102.362) ; C186.2@96.815,15.415 96.815,15.179 v1(97.721,14.272)
  other v1: 31.214,17.701 33.119,17.701 39.977,17.828 41.755,17.828 32.167,18.222 40.891,18.275 31.214,18.717 33.119,18.717 39.977,18.717 41.755,18.717 17.117,29.766 17.879,29.766 18.641,29.766 21.181,29.766 21.943,29.766 22.705,29.766 17.117,30.528 17.879,30.528 18.641,30.528 21.181,30.528 21.943,30.528 22.705,30.528 23.641,31.555 24.551,31.555 24.838,38.439 28.558,38.439 24.039,38.689 26.289,39.37 18.641,39.672 28.614,40.12 24.846,40.224 27.686,40.258 24.039,40.29 18.641,40.434 29.718,41.004 30.477,40.988 30.452,41.745 29.718,41.783 30.48,42.466 29.718,42.517 23.915,43.561 28.714,45.296 28.714,46.058 28.714,46.82 29.349,48.217 30.111,48.217 30.873,48.217 5.56,57.325 53.185,61.262 53.185,62.151 53.185,62.913 49.502,94.663 50.137,94.663 50.772,94.663 50.899,95.425 29.639,150.772 30.046,152.728
GND_EXT_UNFILT: C147.2 CN25.2 CN25.3 L4.3 U43.2 | length 28.6
  Top Layer w0.508: 9.535,31.062 L4.3@10.564,31.062 ; 10.564,30.033 L4.3@10.564,31.062 ; 10.564,32.09 L4.3@10.564,31.062 ; 11.593,31.062 L4.3@10.564,31.062 ; 13.647,25.974 U43.2@15.397,25.974 ; 15.397,25.027 U43.2@15.397,25.974 ; 15.397,26.924 U43.2@15.397,25.974 ; 17.145,25.974 U43.2@15.397,25.974
  Bottom Layer w0.508: 2.621,19.975 CN25.3@3.9,19.977 ; 3.899,17.498 CN25.3@3.9,19.977 ; 3.899,22.454 CN25.3@3.9,19.977 ; 4.722,14.976 CN25.2@7.2,14.977 ; 5.179,19.975 CN25.3@3.9,19.977 ; 7.198,13.698 CN25.2@7.2,14.977 ; 7.198,16.253 CN25.2@7.2,14.977 ; 9.535,31.062 L4.3@10.564,31.062 ; 9.677,14.976 CN25.2@7.2,14.977 ; 10.564,30.033 L4.3@10.564,31.062 ; 10.564,32.09 L4.3@10.564,31.062 ; 11.593,31.062 L4.3@10.564,31.062
  other v1: 14.704,27.48 15.339,27.48 15.974,27.48 16.736,27.48 14.704,28.115 15.339,28.115 15.974,28.115 16.736,28.115
GNDDetect: CN16.11 R187.2 U19.3 U40.K13 | length 74.3
  Top Layer w0.127: U19.3@79.256,76.077 79.266,76.068 v1(79.266,75.054) ; U40.K13@80.755,33.453 v2(81.057,33.756) ; R187.2@80.797,79.708 81.44,79.068 82.141,79.068 82.598,79.525 v1(82.649,79.525) ; v1(86.332,75.74) 86.586,75.74 86.962,76.116 CN16.11@88.258,76.117
  L4_SIG w0.102: v1(79.266,75.054) 79.266,78.199 79.505,78.438 80.206,78.438 81.506,77.137 81.506,73.454 82.014,72.946 82.446,72.946 82.827,72.565 82.827,67.655 77.721,62.55 77.721,39.647 77.925,39.444 77.925,34.745 78.204,34.465 80.348,34.465 v2@81.058,33.757
  Bottom Layer w0.127: v1(79.266,75.054) v1@79.256,75.062 ; v1(86.332,75.74) 85.189,75.74 83.157,77.772 83.157,79.296 82.928,79.525 v1(82.649,79.525) 80.592,79.525 79.169,78.102 v1@79.169,75.207 ; v1@79.169,75.207 79.256,75.121 v1@79.256,75.062 ; v1@79.169,75.207 79.169,75.148 v1@79.256,75.062
I2C3_SCL: CN1.3 R17.1 R73.1 R74.2 R243.1 R258.2 U1.1 U1.6 | length 242.4
  Top Layer w0.127: v1(24.102,108.252) 24.991,109.141 24.991,112.189 28.547,115.745 28.547,120.541 28.674,120.668 28.674,130.858 29.106,131.29 29.106,152.55 29.972,153.416 33.609,153.416 33.96,153.767 33.96,154.457 35.489,155.986 35.489,156.683 35.215,156.957 v1(34.567,156.957) 33.945,157.579 31.547,157.579 30.046,159.08 28.324,159.08 27.991,158.747 R17.1@27.991,158.409 ; CN1.3@27.135,166.429 27.384,166.675 v1(33.5,166.675) ; v1(49.058,135.557) 49.058,134.668 49.08,134.645 R74.2@51.494,134.645 ; R243.1@78.604,46.738 v1(79.299,46.736) ; v1(83.142,39.164) R258.2@83.142,39.934
  L4_SIG w0.102: v1(24.102,108.252) 24.229,108.125 32.865,108.125 33.373,108.633 34.008,108.633 34.897,107.744 34.897,95.425 37.666,92.657 51.636,92.657 54.455,89.837 61.415,89.837 62.329,88.923 62.329,82.966 66.634,78.661 78.707,78.661 79.093,79.047 80.536,79.047 83.436,76.147 83.436,67.13 78.331,62.024 78.331,47.706 v1(79.299,46.736) ; v1(34.567,156.957) 34.776,157.166 40.848,157.166 41.628,156.385 41.628,143.05 49.058,135.621 v1(49.058,135.557)
  Bottom Layer w0.127: v1(33.5,166.675) 34.742,165.433 34.742,157.132 v1(34.567,156.957) ; v1(79.299,46.736) 79.299,43.302 83.142,39.459 v1(83.142,39.164)
I2C3_SDA: CN1.1 R13.1 R78.2 R80.1 R239.1 R257.2 U1.3 U1.4 | length 211.2
  Top Layer w0.127: CN1.1@27.135,168.969 27.526,168.575 v1(33.498,168.575) ; R13.1@29.439,158.409 30.145,158.409 31.366,157.187 33.404,157.187 34.282,156.309 v1@34.567,156.309 ; v1(35.469,107.49) 36.612,108.633 37.437,108.633 38.326,109.522 38.834,109.522 40.764,111.453 40.764,117.93 43.482,120.647 43.482,126.916 47.85,131.284 48.531,131.284 v1(49.058,131.811) 49.058,133.144 49.578,133.665 R78.2@51.51,133.666 ; R239.1@78.579,47.738 v1(79.334,47.737) ; v1(84.468,39.164) R257.2@84.468,39.934
  L4_SIG w0.102: v1(34.567,156.253) 35.156,156.842 40.739,156.842 41.247,156.334 41.247,142.999 48.359,135.887 48.359,135.176 49.058,134.478 v1(49.058,131.811) ; v1(35.469,107.49) 36.294,106.665 36.294,94.536 37.843,92.987 51.813,92.987 54.62,90.18 61.625,90.18 62.659,89.146 62.659,83.067 66.76,78.966 78.58,78.966 78.966,79.352 80.815,79.352 83.767,76.401 83.767,67.028 78.636,61.897 78.636,48.435 v1(79.334,47.737)
  Bottom Layer w0.127: v1(33.498,168.575) 35.12,166.956 35.12,156.807 v1(34.567,156.253) ; v1(79.334,47.737) 79.855,47.216 79.855,43.777 v1(84.468,39.164)
I2C3_SMBA: R15.1 R16.1 R70.2 | length 52.9
  Top Layer w0.127: v5(23.571,155.679) 23.571,156.23 23.849,156.507 R15.1@24.979,156.507 ; R16.1@32.639,155.06 33.358,155.06 33.477,154.94 v1(33.477,154) ; v1(50.724,135.636) R70.2@51.469,135.636
  L4_SIG w0.102: v1(33.477,154) 33.147,154.33 33.147,156.733 33.882,157.468 41.231,157.468 42.136,156.563 42.136,143.177 48.994,136.319 50.038,136.319 v1(50.724,135.636)
  Bottom Layer w0.127: v5(23.571,155.679) 24.738,155.679 26.416,154 v1(33.477,154)
IDD_MEAS: C112.2 R266.2 U32.25 | length 22.2
  Top Layer w0.127: R266.2@49.054,38.314 49.332,38.034 v1(51.13,38.034) ; v1(67.917,42.72) 68.306,43.109 U32.25@68.306,43.79
  L4_SIG w0.102: v1(51.13,38.034) 52.387,39.291 64.488,39.291 v1(67.917,42.72)
JTAG_HOST_NRST: CN14.15 CN15.10 CN17.10 R211.1 U18.1 | length 28.5
  Top Layer w0.127: CN17.10@98.428,74.093 v1(100.302,74.092) ; v1(99.464,82.141) CN15.10@99.464,83.193 ; v1(100.261,79.002) 100.602,78.661 100.805,78.661 101.14,78.326 U18.1@101.542,78.326 ; R211.1@106.991,68.072 v1(107.668,68.072) 110.617,68.072 CN14.15@111.125,68.58
  L4_SIG w0.102: v1(99.464,82.141) 99.464,79.799 v1(100.261,79.002)
  Bottom Layer w0.127: v1(100.261,79.002) 99.54,78.28 99.54,74.854 v1(100.302,74.092) 101.951,74.092 103.223,72.819 104.366,72.819 106.728,70.457 106.728,69.012 v1(107.668,68.072)
JTAG_TCK: CN14.9 CN15.4 CN17.4 R193.1 R195.2 U18.4 | length 28.5
  Top Layer w0.127: CN15.4@95.654,84.463 v1(95.654,85.468) ; CN17.4@98.428,77.903 99.411,77.902 100.239,77.074 v1(100.239,76.693) ; U18.4@103.241,77.026 104.224,77.026 v1(104.239,77.01) 104.696,77.467 106.512,77.467 R193.1@106.99,77.945 ; R193.1@106.99,78.026 R193.1@107.003,78.039 107.003,77.958 R193.1@106.99,77.945 ; CN14.9@111.125,76.2 109.748,76.2 109.052,76.896 R195.2@106.991,76.898 R193.1@106.99,77.945
  L4_SIG w0.102: v1(95.654,85.468) 95.654,80.622 99.583,76.693 v1(100.239,76.693)
  Bottom Layer w0.127: v1(100.239,76.693) 100.556,77.01 v1(104.239,77.01)
JTAG_TDI: CN14.5 CN15.8 CN17.8 R184.1 R185.1 U20.4 | length 33.1
  Top Layer w0.127: v1(96.924,82.09) CN15.8@96.924,83.193 ; CN17.8@98.428,75.363 100.173,75.362 v1(100.683,74.851) 100.747,74.788 100.747,74.28 101.018,74.008 U20.4@101.544,74.008 ; v1(107.795,82.725) R184.1@107.003,82.725 106.975,82.725 107.003,82.697 R185.1@107.003,81.534 110.871,81.534 CN14.5@111.125,81.28
  L4_SIG w0.102: v1(96.924,82.09) 96.924,79.987 99.647,77.264 100.556,77.264 101.064,76.756 101.064,75.232 v1(100.683,74.851)
  Bottom Layer w0.127: v1(96.924,82.09) 98.067,80.947 100.048,80.947 101.318,82.217 107.287,82.217 v1(107.795,82.725)
JTAG_TDO: CN14.13 CN15.6 CN17.6 R197.1 R209.1 R210.2 U18.3 | length 35.1
  Top Layer w0.127: v1(94.384,82.09) CN15.6@94.384,83.193 ; CN17.6@98.428,76.633 98.684,76.375 99.794,76.375 100.302,75.867 v1(100.556,75.867) 101.191,76.502 101.409,76.502 101.542,76.634 101.542,77.026 101.684,77.026 102.207,76.502 v1(102.207,76.248) ; v1(105.382,75.867) R197.1@106.075,75.867 ; v1(107.668,69.342) R210.2@106.991,69.342 R209.1@106.991,70.485 110.49,70.485 CN14.13@111.125,71.12
  L4_SIG w0.102: v1(94.384,82.09) 94.384,80.747 95.273,79.858 95.273,77.854 97.259,75.867 v1(100.556,75.867)
  Bottom Layer w0.127: v1(102.207,76.248) 102.588,75.867 v1(105.382,75.867) 105.89,75.867 107.135,74.623 107.135,69.875 v1(107.668,69.342)
JTAG_TMS: CN14.7 CN15.2 CN17.2 R186.1 R188.1 U18.5 | length 23.3
  Top Layer w0.127: CN15.2@98.194,84.463 v1(98.194,85.316) ; CN17.2@98.428,79.173 99.416,79.172 99.921,79.677 v1(100.302,79.677) 101.318,79.677 102.669,78.326 104.539,78.326 105.001,78.788 106.454,78.788 R188.1@107.003,79.339 106.99,79.35 R186.1@106.991,80.518 109.347,80.518 CN14.7@111.125,78.74
  L4_SIG w0.102: v1(98.194,85.316) 99.413,84.097 99.413,83.36 100.429,82.344 100.429,79.804 v1(100.302,79.677)
JTAG_TRST: CN14.3 CN15.9 R183.1 R205.1 R207.2 U20.3 | length 32.3
  Top Layer w0.127: v1(98.194,82.014) CN15.9@98.194,83.193 ; v1(102.989,74.704) 102.989,74.262 103.243,74.008 104.193,74.008 105.512,72.69 R205.1@106.103,72.69 106.103,71.6 R207.2@106.091,71.59 ; v1(107.003,85.011) R183.1@107.003,84.074 110.871,84.074 CN14.3@111.125,83.82
  L4_SIG w0.102: v1(98.194,82.014) 98.194,79.525 100.073,77.645 100.937,77.645 101.572,77.01 101.572,75.486 102.354,74.704 v1(102.989,74.704)
  Bottom Layer w0.127: v1(98.194,82.014) 98.753,81.455 99.921,81.455 101.191,82.725 102.588,82.725 104.112,84.249 106.241,84.249 v1(107.003,85.011)
JTCK-SWCLK: CN29.1 R47.1 R193.2 R206.2 U40.M11 | length 266.7
  Top Layer w0.127: v1(32.7,106.766) 32.7,108.087 33.627,109.014 34.516,109.014 37.015,111.514 37.986,111.514 38.859,112.387 38.859,118.72 41.577,121.437 41.577,128.013 45.311,131.747 45.311,139.494 50.493,144.676 53.947,144.676 54.226,144.396 54.226,143.863 54.587,143.502 R47.1@54.684,143.502 ; v1(80.162,72.286) R206.2@80.8,72.286 ; U40.M11@82.055,32.154 v2(82.357,32.456) ; v1(105.382,78.039) R193.2@106.091,78.039
  L4_SIG w0.102: v1(32.7,106.766) 32.586,106.652 32.586,95.705 36.853,91.437 50.696,91.437 54.328,87.805 56.614,87.805 60.584,83.835 60.584,82.555 65.999,77.137 75.054,77.137 76.162,76.03 76.162,73.749 77.092,72.819 79.629,72.819 v1(80.162,72.286) 80.617,71.831 80.617,68.146 75.283,62.812 75.283,37.64 74.14,36.497 74.14,31.392 74.648,30.884 74.648,28.141 75.334,27.455 80.084,27.455 80.49,27.861 81.379,27.861 81.887,28.369 81.887,31.984 v2@82.359,32.456
  Bottom Layer w0.127: v1(80.162,72.286) 81.608,72.286 82.141,72.819 82.649,72.819 82.903,73.073 91.412,73.073 92.301,72.184 95.095,72.184 100.073,67.206 107.516,67.206 108.43,68.12 108.43,76.629 107.02,78.039 v1(105.382,78.039) ; v2@82.359,32.456 82.591,32.687 83.792,32.687 84.046,32.941 85.824,32.941 86.713,32.052 86.713,22.654 91.793,17.574 104.099,17.574 CN29.1@108.611,13.066
JTDI: R54.1 R185.2 R199.2 | length 148.7
  Top Layer w0.127: v1(33.627,107.744) 33.876,107.744 37.264,111.133 38.143,111.133 39.24,112.23 39.24,118.562 41.958,121.28 41.958,127.856 45.692,131.59 45.692,138.605 49.121,142.034 51.109,142.034 R54.1@51.16,142.085 ; v1(80.147,74.762) 80.231,74.846 R199.2@80.782,74.846 ; v1(105.303,81.534) R185.2@106.103,81.534
  L4_SIG w0.102: v1(33.627,107.744) 34.135,107.236 34.135,106.347 33.373,105.585 33.373,95.933 37.259,92.047 51.224,92.047 54.679,88.593 60.018,88.593 61.336,87.274 61.336,82.665 66.254,77.747 76.451,77.747 76.807,77.391 76.807,74.878 77.495,74.191 79.576,74.191 v1(80.147,74.762)
  Bottom Layer w0.127: v1(80.147,74.762) 79.677,75.232 79.677,76.451 79.855,76.629 80.363,76.629 80.998,77.264 82.903,77.264 84.935,75.232 87.094,75.232 92.301,80.439 100.302,80.439 101.397,81.534 v1(105.303,81.534)
JTDO-SWO: R107.2 R204.2 R209.2 U40.D12 | length 172
  Top Layer w0.127: v1(33.627,106.728) 33.83,106.931 37.686,106.931 39.007,108.252 40.231,108.252 42.288,110.31 42.288,117.297 48.357,123.365 51.592,123.365 R107.2@51.595,123.393 ; v2(76.551,33.105) U40.D12@76.853,32.803 ; v1(80.19,73.175) 80.338,73.175 80.739,73.576 R204.2@80.823,73.577 ; v1(105.382,70.485) R209.2@106.091,70.485
  L4_SIG w0.102: v1(33.627,106.728) 32.967,106.068 32.967,95.832 37.056,91.742 51.026,91.742 54.582,88.186 56.741,88.186 60.932,83.995 60.932,82.638 66.128,77.442 76.121,77.442 76.502,77.061 76.502,74.752 77.368,73.886 79.479,73.886 v1(80.19,73.175) 80.998,72.367 80.998,67.917 75.664,62.583 75.664,37.513 75.029,36.878 75.029,34.628 v2@76.551,33.106
  Bottom Layer w0.127: v1(80.19,73.175) 80.236,73.175 80.3,73.111 81.163,73.111 82.268,74.216 89.38,74.216 89.939,74.775 93.927,74.775 96.644,72.057 103.81,72.057 v1(105.382,70.485)
JTMS-SWDIO: CN29.2 R44.1 R188.2 R208.2 R285.2 U40.L2 | length 297.9
  Top Layer w0.127: v1(37.424,151.928) 37.424,151.623 37.869,151.178 40.485,151.178 41.12,150.543 41.12,148.392 43.972,145.539 56.284,145.539 56.868,144.955 56.868,144.348 56.946,144.27 R44.1@56.946,143.576 ; v1(80.165,71.029) 80.173,71.036 R208.2@80.83,71.036 ; U40.L2@81.405,26.303 81.709,25.997 81.709,25.143 81.636,25.07 v1(81.636,24.559) R285.2@81.636,23.899 ; v1(105.382,79.337) R188.2@106.103,79.339
  L4_SIG w0.102: v1(37.424,151.928) 36.446,152.905 32.941,152.905 31.925,151.889 31.925,150.569 29.634,148.278 28.819,148.278 22.172,141.628 22.172,135.075 22.832,134.414 22.832,102.41 23.34,101.902 23.34,92.25 24.458,91.133 50.366,91.133 54.049,87.45 56.462,87.45 60.279,83.632 60.279,82.681 60.258,82.66 60.258,82.414 65.865,76.807 74.902,76.807 75.857,75.852 75.857,73.622 77.041,72.438 78.755,72.438 v1(80.165,71.029) 80.165,68.303 74.902,63.04 74.902,37.894 73.81,36.802 73.81,31.163 74.343,30.63 74.343,28.014 75.207,27.15 79.045,27.15 v1(81.636,24.559)
  Bottom Layer w0.127: v1(80.165,71.029) 82.636,71.029 83.411,71.803 91.539,71.803 92.301,71.041 95.552,71.041 99.769,66.825 107.77,66.825 108.862,67.917 108.862,76.959 106.484,79.337 v1(105.382,79.337) ; v1(81.636,24.559) 82.08,24.115 82.08,21.877 82.573,21.384 87.094,21.384 91.412,17.066 102.067,17.066 CN29.2@106.071,13.066
JTRST: R109.1 R205.2 | length 106.3
  Top Layer w0.127: v1(42.822,109.598) 42.822,109.705 43.279,110.162 43.279,111.173 43.05,111.402 43.05,116.982 48.163,122.095 51.313,122.095 R109.1@51.628,122.411 ; R205.2@107.003,72.69 v1(107.668,72.69)
  L4_SIG w0.102: v1(42.822,109.598) 43.304,109.116 47.267,109.116 51.255,105.128 51.255,101.47 55.344,97.381 57.833,97.381 59.337,95.877 63.644,95.877 68.158,91.363 68.158,84.897 68.887,84.168 84.381,84.168 86.738,81.811 89.248,81.811 90.442,80.617 93.266,80.617 94.484,79.399 94.484,77.55 99.344,72.69 v1(107.668,72.69)
LCD_CS: R49.1 R216.1 | length 196.6
  Top Layer w0.127: R49.1@63.19,143.503 v1(63.19,144.145) ; v1(93.571,60.957) 94.31,60.957 R216.1@94.311,60.96
  L4_SIG w0.102: v1(36.027,151.724) 35.608,152.143 33.271,152.143 32.586,151.458 32.586,150.241 29.916,147.571 29.207,147.571 22.908,141.272 22.908,135.456 23.543,134.821 23.543,111.478 25.931,109.09 32.459,109.09 33.602,110.233 40.587,110.233 41.73,109.09 41.73,95.146 42.644,94.231 51.407,94.231 51.661,94.485 55.979,94.485 56.36,94.866 56.919,94.866 58.367,93.419 62.888,93.419 65.656,90.65 65.656,84.275 68.222,81.709 77.038,81.709 77.668,82.339 83.34,82.339 84.833,80.846 84.833,80.515 85.087,80.261 87.704,80.261 88.339,79.626 88.339,62.431 89.253,61.516 93.012,61.516 v1(93.571,60.957)
  Bottom Layer w0.127: v1(36.027,151.724) 36.383,151.724 36.827,151.28 42.085,151.28 45.108,148.257 61.135,148.257 62.405,146.987 62.405,145.793 62.481,145.793 63.19,145.085 v1(63.19,144.145)
LED1: R81.2 R297.2 | length 140
  Top Layer w0.127: R297.2@26.924,8.543 v1(26.924,9.474) ; v1(37.45,108.138) 37.48,108.138 38.484,109.141 38.992,109.141 41.145,111.295 41.145,117.772 43.863,120.49 43.863,126.762 43.94,126.762 47.988,130.81 48.946,130.81 49.629,131.493 49.629,132.382 49.936,132.69 R81.2@51.522,132.69
  Bottom Layer w0.127: v1(26.924,9.474) 26.924,18.923 31.925,23.924 31.925,59.56 36.421,64.056 36.421,86.459 35.024,87.856 35.024,94.917 34.516,95.425 34.516,105.204 35.024,105.712 35.024,108.445 35.441,108.862 36.192,108.862 36.421,108.633 36.942,108.633 37.437,108.138 v1(37.45,108.138)
LED3: R96.2 R299.2 | length 247
  Top Layer w0.127: v1(31.565,9.431) 31.565,8.499 R299.2@31.567,8.5 ; R96.2@82.712,126.451 82.713,126.451 83.449,126.451 88.999,132.001 88.999,137.97 90.142,139.113 90.142,144.722 92.809,147.389 92.809,151.178 v1(93.19,151.559)
  L4_SIG w0.102: v1(93.19,151.559) 99.159,151.559 99.286,151.432 103.35,151.432 104.112,150.67 104.112,134.414 105.636,132.89 105.636,122.222 105.255,121.841 105.255,117.777 105.636,117.396 105.636,109.522 104.772,108.659 104.772,101.021 105.664,100.129 105.664,94.508 108.252,91.92 108.252,67.688 107.541,66.977 96.619,66.977 v1(93.698,64.056)
  Bottom Layer w0.127: v1(31.565,9.431) 32.057,8.938 34.389,8.938 36.294,10.843 36.294,25.067 43.279,32.052 50.239,32.052 52.857,34.671 54.788,34.671 59.789,39.672 59.789,41.958 61.948,44.117 61.948,45.768 62.583,46.403 62.583,47.419 62.964,47.8 65.758,47.8 67.155,49.197 72.108,49.197 72.997,50.086 72.997,60.881 76.68,64.564 93.19,64.564 v1(93.698,64.056)
LED_STLK: R295.2 R296.2 U40.D15 | length 72.7
  Top Layer w0.127: R296.2@37.244,10.761 38.669,10.759 R295.2@38.685,10.777 39.639,10.775 v1(39.774,10.64) ; v2(76.551,35.055) U40.D15@76.853,34.753
  Bottom Layer w0.127: v1(39.774,10.64) 39.774,5.077 41.247,3.604 60.955,3.604 68.91,11.56 68.91,34.315 70.101,35.507 75.486,35.507 75.938,35.055 v2(76.551,35.055)
Loop: TP6.1 U32.14 | length 18.1
  Top Layer w0.127: TP6.1@62.503,65.125 63.421,65.123 66.139,62.405 66.139,55.928 65.568,55.357 65.568,50.737 66.012,50.292 U32.14@66.807,50.292
MC1_Ain: R64.2 SB113.1 | length 93.4
  Top Layer w0.127: R64.2@22.751,137.017 23.34,136.426 v1(23.34,135.989) ; v1(57.49,99.096) 57.048,99.538 57.048,105.399 58.632,106.982 60.006,106.982 60.579,107.556 62.672,109.649 62.68,109.649 62.807,109.776 70.838,109.776 v1(72.616,111.554)
  L4_SIG w0.102: v1(23.34,135.989) 23.873,135.456 23.873,111.605 26.083,109.395 32.332,109.395 33.475,110.538 41.73,110.538 42.238,110.03 47.826,110.03 56.487,101.369 56.487,100.099 v1(57.49,99.096)
  Bottom Layer w0.127: v1(72.616,111.554) 72.108,112.062 72.108,113.088 SB113.1@72.616,113.596
MC1_Bin: R55.2 SB114.1 | length 97.4
  Top Layer w0.127: R55.2@22.751,141.875 v1(23.574,141.049) ; v1(57.528,99.769) 57.528,99.941 57.427,100.043 57.427,105.238 58.791,106.601 60.17,106.601 62.964,109.395 71.346,109.395 73.378,111.427 73.378,111.91 v1(73.886,112.418)
  L4_SIG w0.102: v1(23.574,141.049) 24.254,140.371 24.254,111.656 26.21,109.7 32.205,109.7 33.424,110.919 35.507,110.919 35.938,111.351 43.609,111.351 44.625,110.335 47.953,110.335 56.817,101.47 56.817,100.48 v1(57.528,99.769)
  Bottom Layer w0.127: v1(73.886,112.418) SB114.1@73.886,113.594
MC1_BusVoltage: C4.1 R3.2 SB115.1 | length 114.8
  Top Layer w0.127: R3.2@76.68,157.208 77.826,157.208 77.95,157.333 v1(78.712,157.333) ; v1(76.934,110.284) 79.903,107.315 104.191,107.315 105.052,108.176 v1(105.915,108.176)
  L4_SIG w0.102: v1(78.712,157.333) 80.625,155.42 93.114,155.42 93.647,154.887 97.559,154.887 99.946,152.499 104.005,152.499 105.128,151.376 105.128,135.049 106.779,133.398 106.779,121.714 106.271,121.206 106.271,118.412 106.779,117.904 106.779,109.04 v1(105.915,108.176)
  Bottom Layer w0.127: SB115.1@71.196,113.636 71.196,111.831 73.251,109.776 76.426,109.776 v1(76.934,110.284)
MC1_Cin: R52.2 SB99.1 | length 35.3
  Top Layer w0.127: R52.2@22.751,143.179 v1(22.751,144.732)
  Bottom Layer w0.127: v1(22.751,144.732) 22.751,125.733 25.118,123.365 32.357,123.365 33.246,122.476 v1(34.465,122.476) 35.314,122.476 SB99.1@35.898,121.895
MC1_CurrentA+: C8.2 R2.1 SW5.2 | length 92.2
  Top Layer w0.127: v1(74.14,156.512) 74.14,157.333 75.159,157.333 R2.1@75.283,157.208
  L4_SIG w0.102: v1(11.732,146.301) 13.409,147.978 13.409,156.461 15.542,158.595 22.883,158.595 24.788,160.5 30.198,160.5 30.782,161.084 44.676,161.084 47.013,158.747 49.096,158.747 49.807,158.036 67.917,158.036 68.273,157.681 72.974,157.681 v1(74.14,156.512)
  Bottom Layer w0.127: v1(11.732,146.301) 11.732,143.609 14.526,140.815 14.526,137.31 15.161,136.675 17.424,136.675 SW5.2@18.45,135.65
MC1_CurrentB+: C6.2 R4.1 SW5.5 | length 88.2
  Top Layer w0.127: v1(70.965,160.957) 70.965,157.655 71.288,157.333 72.616,157.333 R4.1@72.726,157.224
  L4_SIG w0.102: v1(11.707,147.876) 11.326,148.257 11.326,155.699 19.022,163.396 46.053,163.396 48.39,161.059 67.18,161.059 67.79,160.449 70.457,160.449 v1(70.965,160.957)
  Bottom Layer w0.127: v1(11.707,147.876) 12.672,146.911 12.672,144.473 14.577,142.568 17.531,142.568 SW5.5@18.45,141.65
MC1_CurrentC+: C2.2 R6.1 SW5.8 | length 84.4
  Top Layer w0.127: v1(68.044,160.957) 68.044,158.346 69.06,157.33 70.079,157.33 R6.1@70.203,157.208
  L4_SIG w0.102: v1(11.681,147.14) 10.97,147.851 10.97,155.801 19.733,164.564 45.387,164.564 48.588,161.364 67.638,161.364 v1(68.044,160.957)
  Bottom Layer w0.127: v1(11.681,147.14) 12.266,146.555 12.266,144.117 14.735,141.648 SW5.8@15.951,141.648
MC1_DissipativeBrake: CN2.23 SB97.1 | length 128.8
  L4_SIG w0.102: v1(9.014,117.701) 8.252,118.463 8.252,155.75 22.121,169.619 62.558,169.619 63.5,168.676 CN2.23@63.5,165.735
  Bottom Layer w0.127: v1(9.014,117.701) 12.926,117.701 15.796,114.831 19.403,114.831 26.695,122.123 SB97.1@30.875,122.125
MC1_EnA: C3.2 CN2.31 SB2.1 SB98.1 | length 105.4
  Top Layer w0.127: CN2.31@53.34,165.735 54.582,164.49 54.582,161.922 53.978,161.318 C3.2@53.977,158.287 54.938,158.285 SB2.1@55.027,158.198 v1(55.027,159.433)
  L4_SIG w0.102: v1(55.027,159.433) 55.179,159.281 60.551,159.281 61.288,160.017 66.901,160.017 67.409,159.509 71.117,159.509 72.057,160.449 93.825,160.449 v1(97,157.274)
  Bottom Layer w0.127: v1(97,157.274) 97.533,157.808 103.401,157.808 106.525,154.683 106.525,133.424 107.287,132.662 107.287,123.111 106.271,122.095 103.604,122.095 103.223,122.476 102.69,122.476 102.184,121.971 SB98.1@100.421,121.971 SB98.1@100.421,121.968
MC1_EnB: C9.2 CN2.33 SB89.1 | length 51.1
  Top Layer w0.127: v1(42.466,157.325) 43.373,158.232 48.486,158.232 C9.2@48.486,158.235 48.486,163.421 CN2.33@50.8,165.735
  L4_SIG w0.102: v1(42.466,157.325) 43.584,156.207 43.584,149.121 48.257,144.447 49.883,144.447 51.915,142.415 51.915,129.461 v1(50.292,127.838)
  Bottom Layer w0.127: v1(50.292,127.838) SB89.1@51.497,127.838
MC1_EnIndex: C11.2 CN2.34 SB62.1 SB92.1 | length 65
  Top Layer w0.127: v1(40.485,156.157) 41.095,156.766 46.2,156.766 46.962,156.004 48.821,156.004 49.075,156.258 49.075,158.062 49.195,158.181 C11.2@49.654,158.181 49.654,162.049 CN2.34@50.8,163.195
  L4_SIG w0.102: v1(40.485,156.157) 40.866,155.776 40.866,147.114 37.579,143.828 34.755,143.828 v1(34.389,143.462) 34.389,143.05 35.786,141.653 39.748,141.653 42.441,138.961 42.441,132.458 v1(50.289,124.612)
  Bottom Layer w0.127: v1(34.389,143.462) 34.564,143.637 SB62.1@35.949,143.637 ; v1(50.289,124.612) SB92.1@51.494,124.612
MC1_ICL_SHUTOUT: CN2.21 SB109.1 | length 165.4
  L4_SIG w0.102: v1(8.938,116.99) 7.948,117.98 7.948,155.877 21.994,169.923 62.687,169.923 66.04,166.573 CN2.21@66.04,165.735
  Bottom Layer w0.127: v1(8.938,116.99) 13.053,112.875 19.835,112.875 22.527,115.567 34.313,115.567 37.005,112.875 47.8,112.875 50.239,110.437 59.56,110.437 61.567,112.443 61.567,112.697 62.202,113.332 SB109.1@62.202,113.721
MC1_MC2_PFC_Ind: C7.2 C29.2 R5.2 R113.2 SB55.1 | length 129.8
  Top Layer w0.127: v1(11.184,123.187) 11.184,121.331 R113.2@11.36,121.158 ; v1(61.923,168.984) 62.253,168.653 62.253,162.329 62.888,161.694 62.888,157.579 63.282,157.185 R5.2@63.634,157.187 ; R5.2@63.634,157.187 63.833,157.386 64.816,157.386 64.869,157.333 v1(64.869,155.445)
  L4_SIG w0.102: v1(11.184,123.187) 9.878,124.493 9.878,129.588 9.243,130.223 9.243,134.164 9.878,134.799 9.878,156.004 19.428,165.555 44.549,165.555 48.257,169.263 61.643,169.263 v1(61.923,168.984) ; v1(64.869,155.445) 65.377,154.937 65.377,152.067 66.139,151.305 70.152,151.305 74.724,146.733 77.061,146.733 77.95,145.844 v1(77.95,145.311)
  Bottom Layer w0.127: SB55.1@77.823,144.447 77.95,144.574 v1(77.95,145.311)
MC1_MC2_PFC_SD: R10.2 R128.2 SB17.1 | length 106.1
  Top Layer w0.127: R128.2@11.36,114.681 11.783,114.681 15.926,110.538 v1(23.721,110.538) ; v1(39.723,109.141) 41.526,110.945 41.526,117.612 44.244,120.33 44.244,126.531 47.937,130.223 49.629,130.223 50.317,129.535 v1(50.317,129.515) SB17.1@51.493,129.515 ; v1(42.949,156.08) 45.413,156.08 46.048,155.445 55.293,155.445 56.36,156.512 R10.2@56.36,156.954
  L4_SIG w0.102: v1(23.721,110.538) 25.474,108.786 32.611,108.786 33.754,109.929 38.936,109.929 v1(39.723,109.141) ; v1(42.949,156.08) 43.152,155.877 43.152,148.968 48.308,143.812 49.883,143.812 51.61,142.085 51.61,130.807 v1(50.317,129.515)
MC1_MC2_PFC_Vac: C10.2 C34.2 R12.2 R155.2 SB56.1 | length 137.2
  Top Layer w0.127: R155.2@11.36,111.252 11.118,111.493 C34.2@11.118,112.268 v1(12.098,112.268) ; v1(50.264,159.56) 50.264,159.131 50.188,159.055 50.188,157.914 50.264,157.838 C10.2@50.772,157.333 ; v1(50.772,156.639) C10.2@50.772,157.333 ; R12.2@51.915,156.954 51.915,156.957 51.539,157.333 C10.2@50.772,157.333 ; v1(71.498,155.725) 71.676,155.725 72.431,154.97 72.431,151.745 75.664,148.511 75.664,145.926 75.184,145.445 v1(75.184,145.285)
  L4_SIG w0.102: v1(12.098,112.268) 9.675,114.691 9.675,117.853 8.583,118.946 8.583,155.598 19.2,166.215 41.272,166.215 v1(41.679,166.621) ; v1(50.772,156.639) 50.899,156.766 59.789,156.766 60.754,155.801 63.523,155.801 64.234,156.512 66.825,156.512 67.612,155.725 v1(71.498,155.725)
  Bottom Layer w0.127: v1(41.679,166.621) 41.679,164.335 44.676,161.338 48.486,161.338 v1(50.264,159.56) ; SB56.1@75.183,144.223 75.184,144.224 v1(75.184,145.285)
MC1_MC2_PFCpwm: R11.1 R151.1 SB118.1 | length 149.8
  Top Layer w0.127: R151.1@11.36,113.41 11.834,113.408 v1(12.164,113.078) ; v1(47.013,111.097) 53.363,111.097 v1(54.201,111.935) ; v1(57.122,159.713) 57.122,157.716 R11.1@57.884,156.954
  L4_SIG w0.102: v1(12.164,113.078) 10.107,115.136 10.107,117.955 8.887,119.174 8.887,155.471 19.301,165.885 41.755,165.885 v1(42.415,166.545)
  Bottom Layer w0.127: v1(12.164,113.078) 13.221,112.022 32.977,112.022 33.47,111.529 46.581,111.529 v1(47.013,111.097) ; v1(42.415,166.545) 42.415,164.361 44.93,161.846 55.014,161.846 57.122,159.738 v1(57.122,159.713) ; v1(54.201,111.935) 54.836,112.57 54.836,112.994 SB118.1@55.253,113.411
MC1_MC2_PFCsync: R8.1 R126.1 SB103.1 | length 123.5
  Top Layer w0.127: R126.1@11.36,115.951 v1(11.359,116.888) ; v1(59.535,156.253) R8.1@59.535,156.954
  L4_SIG w0.102: v1(11.359,116.888) 12.339,117.869 12.339,124.181 10.64,125.88 10.64,134.16 11.859,135.38 11.859,145.24 14.91,148.29 14.91,148.92 14.45,149.38 14.45,156.069 15.961,157.579 23.315,157.579 24.407,158.671 25.702,158.671 26.058,159.027 30.706,159.027 31.392,159.713 43.609,159.713 47.61,155.712 55.306,155.712 56.055,156.461 59.327,156.461 v1(59.535,156.253)
  Bottom Layer w0.127: v1(11.359,116.888) 11.359,115.28 13.266,113.373 18.656,113.373 26.49,121.206 33.373,121.206 33.881,120.698 33.881,120.47 35.047,119.304 SB103.1@35.796,119.304
MC1_PWM_1H: CN2.3 SB78.1 | length 39.5
  Top Layer w0.127: v1(84.071,132.766) 84.704,133.398 85.011,133.398 87.678,136.065 87.678,138.529 88.872,139.723 88.872,145.113 91.666,147.907 91.666,153.794 87.729,157.731 87.729,164.564 CN2.3@88.9,165.735
  Bottom Layer w0.127: SB78.1@82.967,132.766 v1(84.071,132.766)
